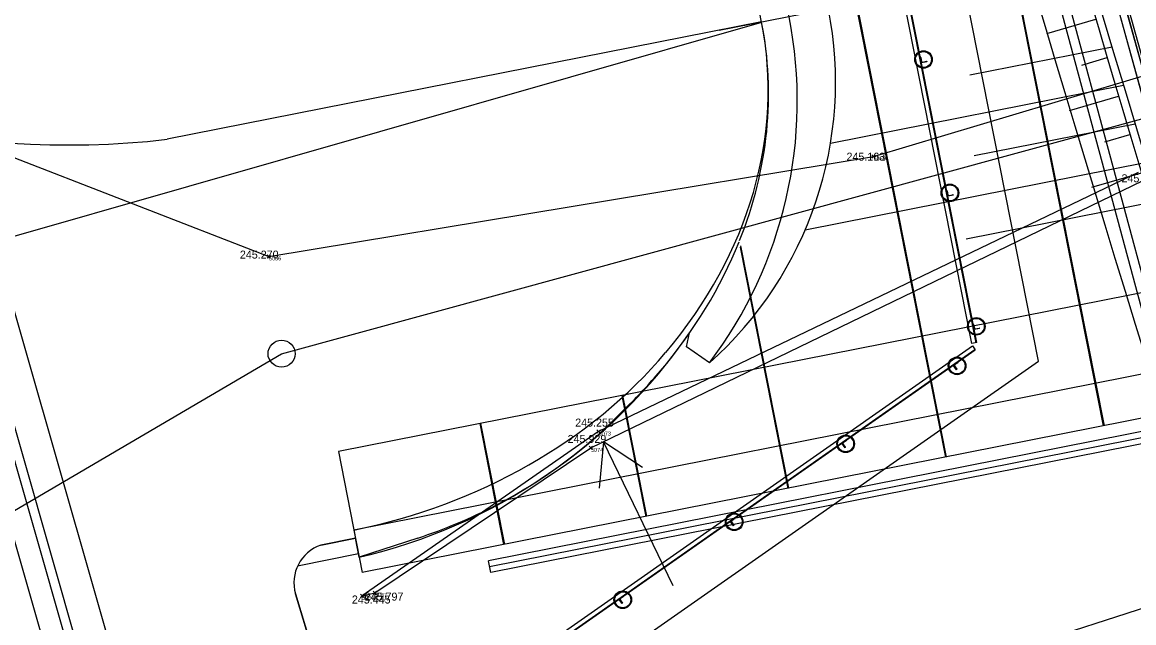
# Model space of a CAD drawing. Extents: x -809973 to -809318, y -1011363 to -1010505.
# Drawn here: x -809855.63 to -809841.74, y -1010996.1 to -1010988.6 of the extents above; entities that cross this region are included whole.
import ezdxf

# ---------------------------------------------------------------- set-up
doc = ezdxf.new("R2010")
doc.units = 0
for name, color, linetype in [('18b - zaměření - čísla bodů', 7, 'Continuous'), ('18c - zaměření - výšky', 7, 'Continuous'), ('21 - sítě', 7, 'Continuous'), ('21a - sítě - DKK - ČD Telematika a.s.', 7, 'Continuous'), ('21b - sítě - SŽDC - SSZT', 7, 'Continuous'), ('21d - sítě - obnova rybníku a obnova náhonu pro rybník', 7, 'Continuous'), ('SO04 - Železniční spodek', 7, 'Continuous'), ('SO05 - Úprava kabelů', 7, 'Continuous'), ('SO_01', 7, 'Continuous'), ('SO_Bubliny', 7, 'Continuous'), ('stav_stav', 7, 'Continuous')]:
    doc.layers.add(name, color=color, linetype=linetype)

# ---------------------------------------------------------------- blocks, each defined once
blk = doc.blocks.new('POINT_DISPLAY')
for p, q in [((-0.021, -0.021), (0.021, 0.021)), ((-0.021, 0.021), (0.021, -0.021))]:
    blk.add_line(p, q)

msp = doc.modelspace()

# ---------------------------------------------------------------- linework, layer by layer
at = {"layer": '21 - sítě'}
msp.add_lwpolyline([(-809832.875, -1011017.263), (-809833.494, -1011015.746), (-809838.391, -1011005.426), (-809840.703, -1011001.729), (-809840.806, -1011000.123), (-809839.446, -1010997.434), (-809844.081, -1010980.644), (-809845.074, -1010978.711), (-809846.471, -1010977.412)], dxfattribs=at)
at = {"layer": '21a - sítě - DKK - ČD Telematika a.s.'}
msp.add_lwpolyline([(-809840.802, -1011000.183), (-809839.446, -1010997.434), (-809844.081, -1010980.644), (-809845.074, -1010978.711), (-809846.471, -1010977.412)], dxfattribs=at)
at = {"layer": '21b - sítě - SŽDC - SSZT'}
msp.add_lwpolyline([(-809840.802, -1011000.183), (-809839.446, -1010997.434), (-809844.081, -1010980.644), (-809845.074, -1010978.711), (-809846.471, -1010977.412)], dxfattribs=at)
at = {"layer": '21d - sítě - obnova rybníku a obnova náhonu pro rybník'}
msp.add_lwpolyline([(-809884.652, -1011011.671), (-809852.391, -1010992.741), (-809838.71, -1010989.006), (-809826.649, -1010985.714), (-809807.016, -1010985.926), (-809784.688, -1010978.607)], dxfattribs=at)
msp.add_circle((-809852.391, -1010992.741), 0.169, dxfattribs=at)
at = {"layer": 'SO04 - Železniční spodek'}
for points in [[(-809842.826, -1010988.74), (-809842.213, -1010988.561)], [(-809842.389, -1010989.133), (-809842.072, -1010989.04)], [(-809842.545, -1010989.7), (-809841.93, -1010989.52)], [(-809842.102, -1010990.091), (-809841.787, -1010989.999)], [(-809842.264, -1010990.66), (-809841.644, -1010990.478)]]:
    msp.add_lwpolyline(points, dxfattribs=at)
for centre, radius, start, end in [((-809453.305, -1010872.818), 406.4, 193.63597, 201.43276), ((-809524.411, -1010895.31), 331.2, 194.62152, 202.36706)]:
    msp.add_arc(centre, radius, start, end, dxfattribs=at)
at = {"layer": 'SO05 - Úprava kabelů'}
for points in [[(-809832.494, -1011018.409), (-809834.046, -1011017.811), (-809840.102, -1011020.003), (-809840.886, -1011019.699), (-809849.784, -1011002.747), (-809854.105, -1010999.74), (-809859.871, -1010979.608), (-809861.054, -1010971.463), (-809873.181, -1010917.053), (-809875.79, -1010892.925), (-809862.192, -1010877.803), (-809870.3, -1010824.924)], [(-809832.452, -1011018.3), (-809834.045, -1011017.686), (-809840.101, -1011019.878), (-809840.803, -1011019.606), (-809849.694, -1011002.668), (-809854.004, -1010999.668), (-809859.756, -1010979.584), (-809860.94, -1010971.442), (-809873.066, -1010917.034), (-809875.669, -1010892.964), (-809862.069, -1010877.84), (-809862.069, -1010877.84), (-809870.184, -1010824.906)], [(-809832.452, -1011018.3), (-809834.599, -1011012.541), (-809836.558, -1011007.657), (-809839.63, -1011000.177), (-809840.754, -1010995.474), (-809845.885, -1010976.431), (-809847.466, -1010970.457), (-809849.998, -1010958.97), (-809853.746, -1010939.574), (-809862.448, -1010886.367), (-809861.681, -1010881.903), (-809870.184, -1010824.906)], [(-809832.343, -1011018.259), (-809834.49, -1011012.499), (-809836.45, -1011007.613), (-809839.519, -1011000.141), (-809840.641, -1010995.445), (-809845.773, -1010976.401), (-809847.353, -1010970.429), (-809849.884, -1010958.947), (-809853.631, -1010939.554), (-809862.33, -1010886.367), (-809861.563, -1010881.905), (-809870.069, -1010824.889)]]:
    msp.add_lwpolyline(points, dxfattribs=at)
msp.add_lwpolyline([(-809855.073, -1010997.359), (-809859.329, -1010982.499), (-809858.576, -1010982.283), (-809854.32, -1010997.143)], close=True, dxfattribs=at)
at = {"layer": 'SO_01'}
for p, q in [((-809844.364, -1010982.306), (-809842.121, -1010993.644)), ((-809844.354, -1010982.304), (-809842.111, -1010993.642)), ((-809846.336, -1010982.696), (-809844.093, -1010994.034)), ((-809846.326, -1010982.694), (-809844.083, -1010994.032)), ((-809843.762, -1010992.614), (-809845.489, -1010983.883)), ((-809843.708, -1010992.603), (-809845.435, -1010983.872)), ((-809843.703, -1010992.602), (-809845.43, -1010983.871)), ((-809830.791, -1010985.512), (-809846.92, -1010988.702)), ((-809846.393, -1010988.591), (-809853.822, -1010990.061)), ((-809825.262, -1010988.739), (-809851.681, -1010993.965)), ((-809842.011, -1010988.909), (-809843.789, -1010989.261)), ((-809841.867, -1010989.39), (-809845.53, -1010990.115)), ((-809825.951, -1010989.895), (-809851.487, -1010994.946)), ((-809841.723, -1010989.871), (-809843.735, -1010990.269)), ((-809824.964, -1010990.25), (-809851.382, -1010995.475)), ((-809841.578, -1010990.352), (-809845.847, -1010991.197)), ((-809841.432, -1010990.833), (-809843.835, -1010991.308)), ((-809827.49, -1010990.916), (-809849.805, -1010995.33)), ((-809827.475, -1010990.99), (-809849.791, -1010995.404)), ((-809827.46, -1010991.063), (-809849.776, -1010995.477)), ((-809846.654, -1010991.393), (-809846.055, -1010994.422)), ((-809846.661, -1010991.41), (-809846.065, -1010994.424)), ((-809849.82, -1010996.885), (-809843.756, -1010992.643)), ((-809843.703, -1010992.602), (-809843.762, -1010992.614)), ((-809843.756, -1010992.643), (-809843.722, -1010992.692)), ((-809849.789, -1010996.93), (-809843.725, -1010992.688)), ((-809849.786, -1010996.934), (-809843.722, -1010992.692)), ((-809848.139, -1010993.264), (-809847.84, -1010994.775)), ((-809848.134, -1010993.29), (-809848.105, -1010993.435)), ((-809848.129, -1010993.262), (-809847.831, -1010994.773)), ((-809848.125, -1010993.282), (-809848.097, -1010993.426)), ((-809849.915, -1010993.615), (-809849.616, -1010995.126)), ((-809849.905, -1010993.614), (-809849.606, -1010995.124)), ((-809851.681, -1010993.965), (-809851.382, -1010995.475)), ((-809849.765, -1010994.374), (-809849.713, -1010994.636)), ((-809849.756, -1010994.369), (-809849.704, -1010994.631)), ((-809851.487, -1010994.946), (-809851.42, -1010995.284)), ((-809851.901, -1010995.133), (-809851.467, -1010995.047)), ((-809850.689, -1010995.045), (-809851.42, -1010995.284)), ((-809851.428, -1010995.244), (-809852.191, -1010995.395)), ((-809849.776, -1010995.477), (-809849.805, -1010995.33)), ((-809840.011, -1010995.405), (-809845.671, -1010997.224)), ((-809850.384, -1011001.803), (-809852.218, -1010995.743))]:
    msp.add_line(p, q, dxfattribs=at)
for points in [[(-809852.218, -1010995.743), (-809851.588, -1010997.824), (-809849.462, -1010997.404), (-809842.929, -1010992.833), (-809844.802, -1010983.363)], [(-809844.395, -1010989.105), (-809844.409, -1010989.036), (-809844.406, -1010989.036)], [(-809844.401, -1010989.039), (-809844.391, -1010989.088)], [(-809844.327, -1010989.089), (-809844.326, -1010989.091), (-809844.395, -1010989.105)], [(-809844.381, -1010989.095), (-809844.332, -1010989.085)], [(-809844.065, -1010990.772), (-809844.079, -1010990.704), (-809844.076, -1010990.703)], [(-809844.071, -1010990.707), (-809844.062, -1010990.755)], [(-809843.997, -1010990.756), (-809843.997, -1010990.759), (-809844.065, -1010990.772)], [(-809844.051, -1010990.763), (-809844.002, -1010990.753)], [(-809847.044, -1010992.856), (-809847.332, -1010992.656), (-809847.291, -1010992.479)], [(-809843.735, -1010992.44), (-809843.749, -1010992.372), (-809843.747, -1010992.371)], [(-809843.741, -1010992.375), (-809843.732, -1010992.423)], [(-809843.667, -1010992.424), (-809843.667, -1010992.427), (-809843.735, -1010992.44)], [(-809843.721, -1010992.43), (-809843.673, -1010992.421)], [(-809843.997, -1010992.884), (-809843.939, -1010992.844), (-809843.938, -1010992.846)], [(-809843.954, -1010992.94), (-809843.956, -1010992.942), (-809843.997, -1010992.884)], [(-809843.982, -1010992.893), (-809843.953, -1010992.934)], [(-809843.939, -1010992.853), (-809843.979, -1010992.881)], [(-809845.39, -1010993.859), (-809845.332, -1010993.819), (-809845.331, -1010993.821)], [(-809845.347, -1010993.915), (-809845.349, -1010993.916), (-809845.39, -1010993.859)], [(-809845.375, -1010993.868), (-809845.346, -1010993.908)], [(-809845.332, -1010993.827), (-809845.372, -1010993.855)], [(-809846.783, -1010994.833), (-809846.725, -1010994.793), (-809846.724, -1010994.795)], [(-809846.74, -1010994.889), (-809846.742, -1010994.891), (-809846.783, -1010994.833)], [(-809846.768, -1010994.842), (-809846.739, -1010994.883)], [(-809846.725, -1010994.801), (-809846.765, -1010994.83)], [(-809851.42, -1010995.284), (-809851.467, -1010995.047), (-809851.901, -1010995.133)], [(-809848.176, -1010995.808), (-809848.118, -1010995.768), (-809848.117, -1010995.77)], [(-809848.133, -1010995.864), (-809848.135, -1010995.865), (-809848.176, -1010995.808)], [(-809848.161, -1010995.817), (-809848.132, -1010995.857)], [(-809848.118, -1010995.776), (-809848.158, -1010995.804)]]:
    msp.add_lwpolyline(points, dxfattribs=at)
for centre, radius in [((-809844.368, -1010989.064), 0.11), ((-809844.368, -1010989.064), 0.1), ((-809844.038, -1010990.731), 0.11), ((-809844.038, -1010990.731), 0.1), ((-809843.708, -1010992.399), 0.11), ((-809843.708, -1010992.399), 0.1), ((-809843.948, -1010992.893), 0.11), ((-809843.948, -1010992.893), 0.1), ((-809845.341, -1010993.867), 0.11), ((-809845.341, -1010993.867), 0.1), ((-809846.734, -1010994.842), 0.11), ((-809846.734, -1010994.842), 0.1), ((-809848.127, -1010995.816), 0.11), ((-809848.127, -1010995.816), 0.1)]:
    msp.add_circle(centre, radius, dxfattribs=at)
for centre, radius, start, end in [((-809483.868, -1010882.207), 373.7, 195.00213, 199.87467), ((-809851.37, -1010989.582), 5.425, 322.8796, 59.4974), ((-809850.165, -1010989.344), 4.698, 311.6222, 70.7548), ((-809855.053, -1010979.444), 10.688, 234.89, 276.613), ((-809844.405, -1010989.04), 0.0045, 11.1885, 101.1886), ((-809844.383, -1010989.086), 0.009, 191.1885, 281.1886), ((-809844.331, -1010989.09), 0.0045, 11.1885, 101.1886), ((-809844.076, -1010990.708), 0.0045, 11.1885, 101.1886), ((-809844.053, -1010990.754), 0.009, 191.1885, 281.1886), ((-809844.002, -1010990.757), 0.0045, 11.1885, 101.1886), ((-809852.976, -1010988.55), 6.911, 283.0168, 325.3526), ((-809843.746, -1010992.375), 0.0045, 11.1885, 101.1886), ((-809843.723, -1010992.421), 0.009, 191.1885, 281.1886), ((-809843.672, -1010992.425), 0.0045, 11.1885, 101.1886), ((-809843.974, -1010992.888), 0.009, 124.9746, 214.9747), ((-809843.941, -1010992.849), 0.0045, 304.9746, 34.9747), ((-809843.957, -1010992.937), 0.0045, 304.9746, 34.9747), ((-809845.367, -1010993.863), 0.009, 124.9746, 214.9747), ((-809845.334, -1010993.823), 0.0045, 304.9746, 34.9747), ((-809845.35, -1010993.911), 0.0045, 304.9746, 34.9747), ((-809846.76, -1010994.837), 0.009, 124.9746, 214.9747), ((-809846.727, -1010994.798), 0.0045, 304.9746, 34.9747), ((-809846.743, -1010994.885), 0.0045, 304.9746, 34.9747), ((-809851.737, -1010995.605), 0.5, 109.1272, 195.9819), ((-809851.737, -1010995.605), 0.5, 109.1272, 195.9819), ((-809848.153, -1010995.812), 0.009, 124.9746, 214.9747), ((-809848.12, -1010995.772), 0.0045, 304.9746, 34.9747), ((-809848.136, -1010995.86), 0.0045, 304.9746, 34.9747)]:
    msp.add_arc(centre, radius, start, end, dxfattribs=at)
for centre, major_axis, ratio, start_param, end_param in [((-809853.013, -1010989.907), (6.622, 1.31), 0.8, 6.283185, 7.068583), ((-809853.013, -1010989.907), (6.622, 1.31), 0.8, 5.497787, 6.283185), ((-809853.381, -1010989.98), (6.99, 1.383), 0.800068, 5.804756, 6.283146), ((-809853.381, -1010989.98), (6.99, 1.383), 0.8, 5.497787, 5.801717), ((-809852.461, -1010990.194), (5.947, 1.176), 0.8, 4.717975, 5.497787), ((-809852.829, -1010990.267), (6.315, 1.249), 0.8, 5.388601, 5.497787), ((-809852.458, -1010990.194), (5.722, 1.132), 0.882873, 5.033427, 5.386405), ((-809852.458, -1010990.194), (5.722, 1.132), 0.882873, 4.848896, 5.031621)]:
    msp.add_ellipse(centre, major_axis=major_axis, ratio=ratio, start_param=start_param, end_param=end_param, dxfattribs=at)
at = {"layer": 'SO_Bubliny'}
msp.add_line((-809846.391, -1010988.599), (-809871.827, -1010995.884), dxfattribs=at)
at = {"layer": 'stav_stav'}
for p, q in [((-809839.446, -1010997.434), (-809844.081, -1010980.644)), ((-809839.345, -1010997.42), (-809843.876, -1010981.071)), ((-809839.358, -1010997.434), (-809843.865, -1010981.05)), ((-809839.322, -1010997.364), (-809842.539, -1010985.783)), ((-809844.992, -1010990.276), (-809835.966, -1010987.57)), ((-809856.658, -1010989.933), (-809852.549, -1010991.524)), ((-809852.549, -1010991.524), (-809844.992, -1010990.276)), ((-809848.524, -1010993.918), (-809841.495, -1010990.513)), ((-809841.685, -1010990.477), (-809848.428, -1010993.714)), ((-809848.428, -1010993.714), (-809851.384, -1010995.767)), ((-809847.496, -1010995.642), (-809848.368, -1010993.842)), ((-809851.225, -1010995.731), (-809848.524, -1010993.918)), ((-809851.384, -1010995.767), (-809851.225, -1010995.731))]:
    msp.add_line(p, q, dxfattribs=at)
msp.add_lwpolyline([(-809847.88, -1010994.162), (-809848.368, -1010993.842), (-809848.42, -1010994.423)], dxfattribs=at)
msp.add_ellipse((-809841.093, -1010989.234), major_axis=(-1.62, 5.315), ratio=0.003059, start_param=6.189212, end_param=9.436189, dxfattribs=at)

# ---------------------------------------------------------------- block references
at = {"layer": '18b - zaměření - čísla bodů'}
for p in [(-809844.992, -1010990.276), (-809852.549, -1010991.524), (-809848.428, -1010993.714), (-809848.524, -1010993.918), (-809851.384, -1010995.767), (-809851.225, -1010995.731)]:
    msp.add_blockref('POINT_DISPLAY', p, dxfattribs=at)

# ---------------------------------------------------------------- texts
for s, p in [('5059', (-809844.992, -1010990.326)), ('5056', (-809852.549, -1010991.574)), ('5073', (-809848.428, -1010993.764)), ('5074', (-809848.524, -1010993.968)), ('5066', (-809851.384, -1010995.817)), ('5067', (-809851.225, -1010995.781))]:
    msp.add_text(s, height=0.05, dxfattribs=at).set_placement(p)
at = {"layer": '18c - zaměření - výšky'}
for s, p in [('245.163', (-809845.33, -1010990.328)), ('245.265', (-809841.893, -1010990.598)), ('245.270', (-809852.912, -1010991.552)), ('245.255', (-809848.721, -1010993.652)), ('245.929', (-809848.816, -1010993.856)), ('245.445', (-809851.512, -1010995.863)), ('245.797', (-809851.352, -1010995.827))]:
    msp.add_text(s, height=0.1, dxfattribs=at).set_placement(p)

doc.saveas('drawing.dxf')
